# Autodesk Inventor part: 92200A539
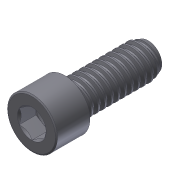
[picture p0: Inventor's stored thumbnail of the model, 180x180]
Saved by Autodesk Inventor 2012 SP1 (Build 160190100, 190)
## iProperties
Created: 2012-03
Part Number: 92200A539
Material: Stainless Steel
Document SubType Name: Modeling
Designer: jdh
Mass: 6.50597 g
Surface Area: 7.95113 cm^2
Volume: 0.805195 cm^3
Density: 8.08 g/cm^3
Author: jdh
Translation Standard: STEP AP203
FileName: 92200A539.step
PreProcessor: SolidWorks 2003314
PostProcessor: Build: 190, Release: 2012 SP1 - Date: Mon 08/08/2011
Sent Units: inch
Uncertainty: 1e-05
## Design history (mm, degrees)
node "92200A5391"
node "NONE"
node "Base1"
